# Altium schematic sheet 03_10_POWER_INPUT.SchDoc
size 289 x 400 mm
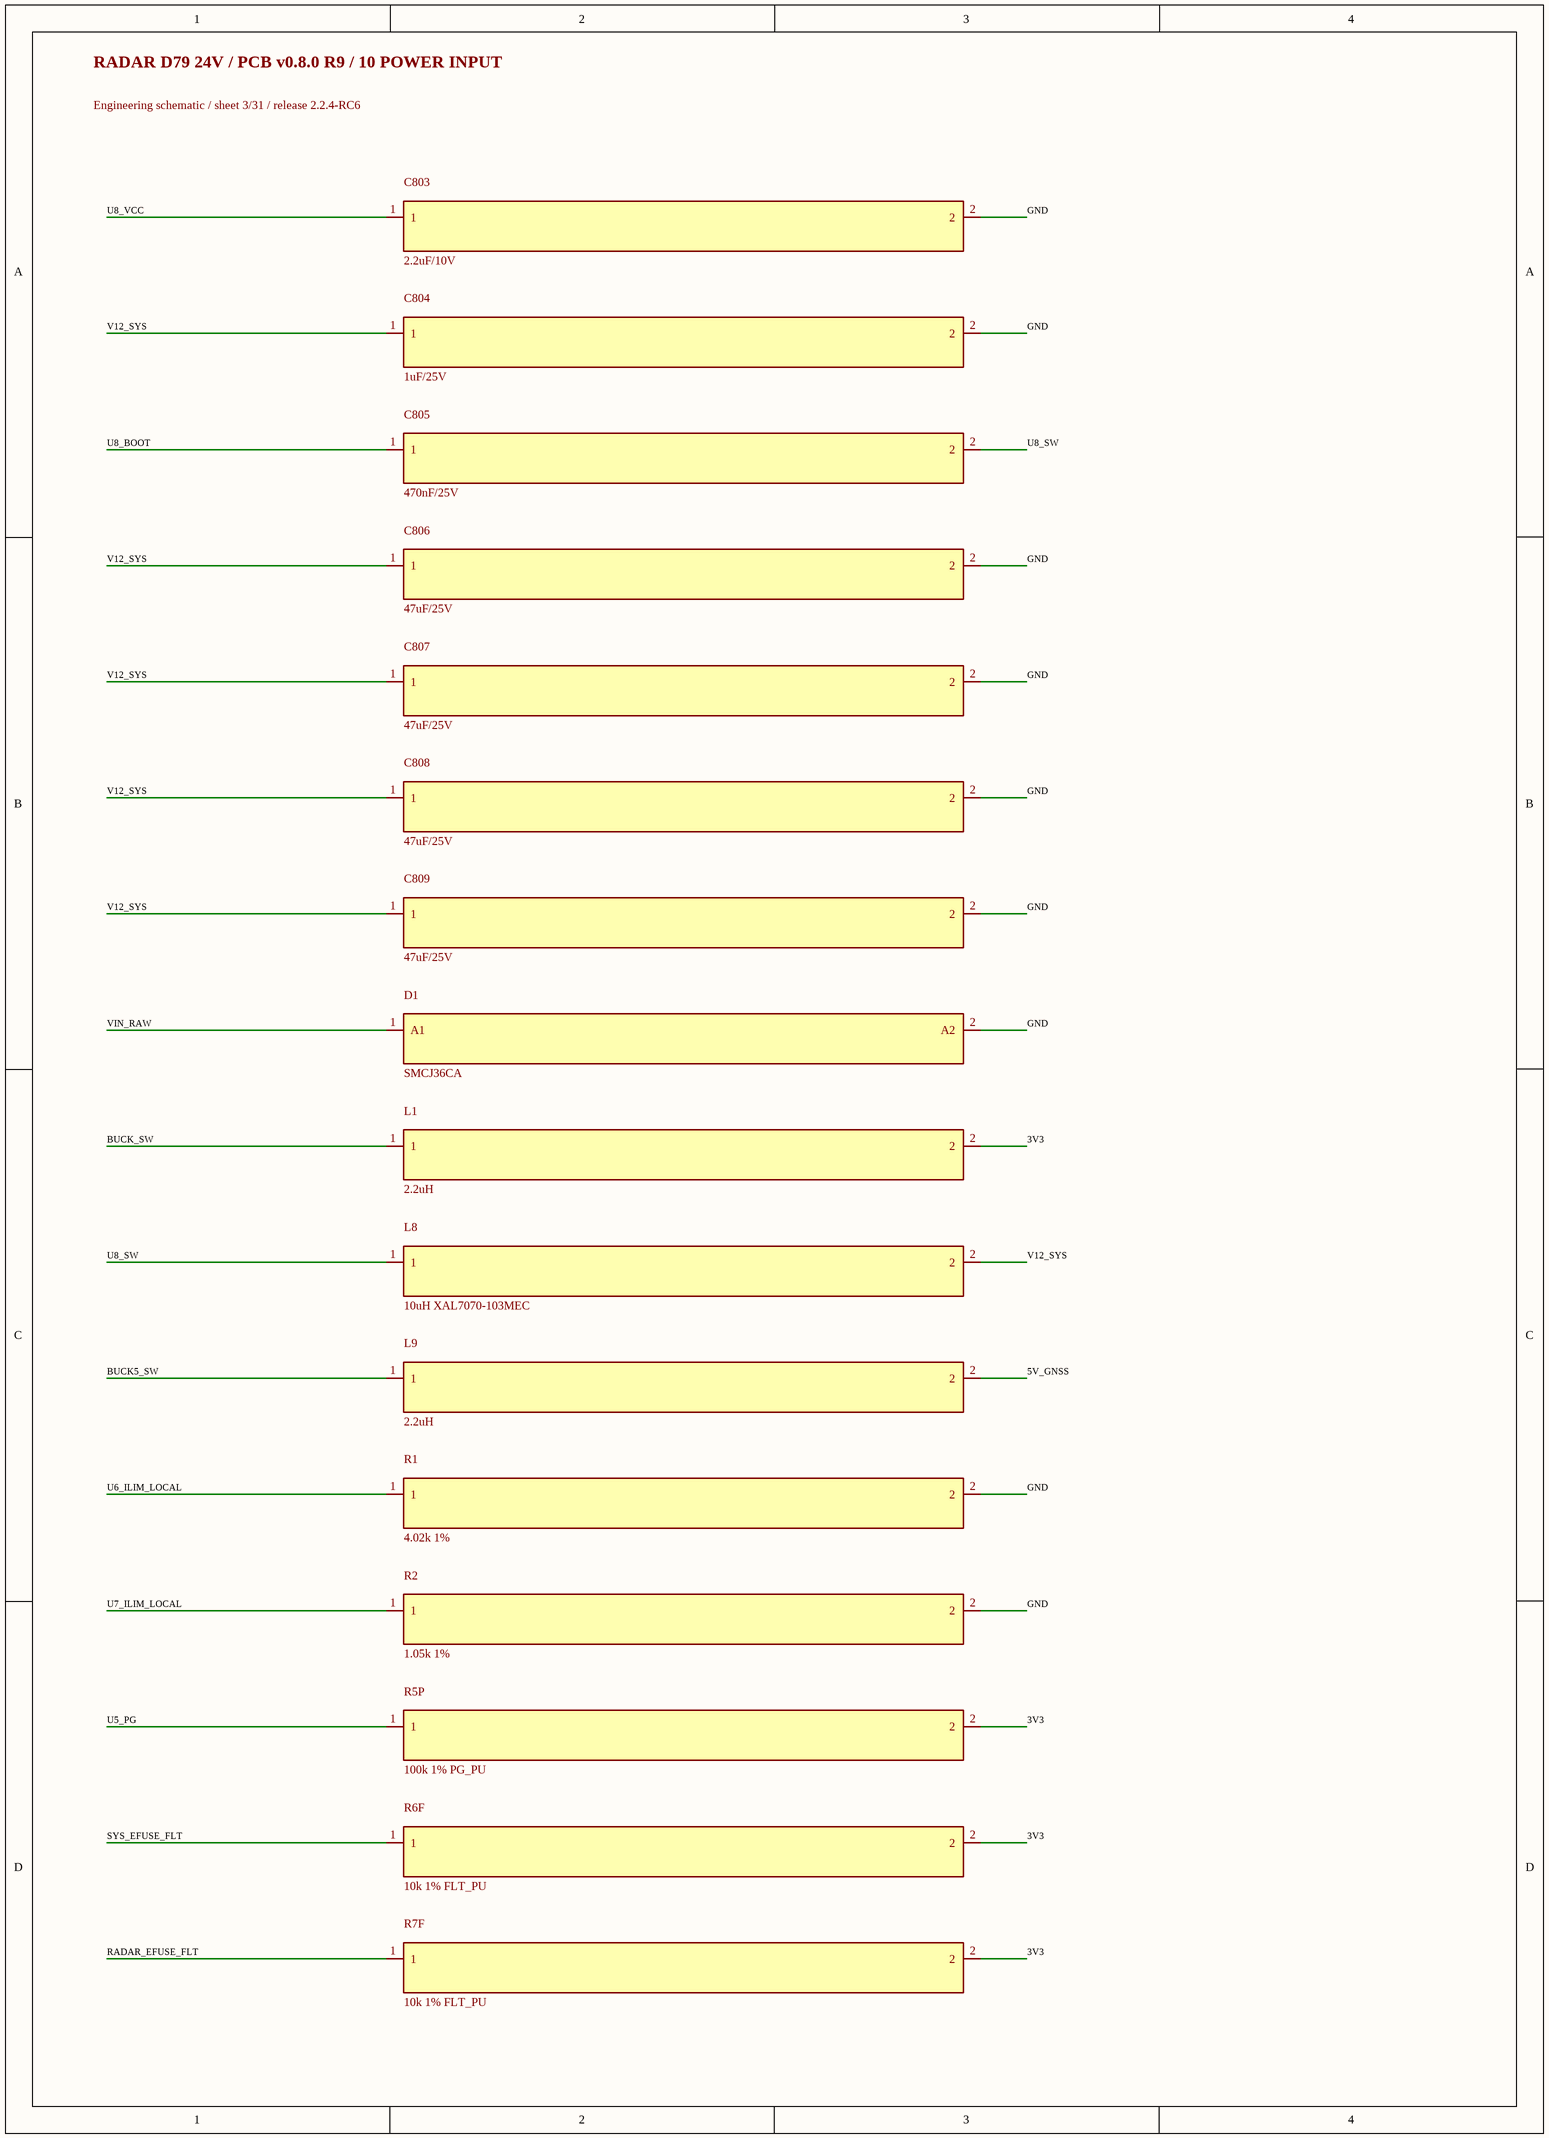
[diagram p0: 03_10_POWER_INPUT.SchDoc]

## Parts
C803  2.2uF/10V  [C_0603_1608Metric]
C804  1uF/25V  [C_0603_1608Metric]
C805  470nF/25V  [C_0603_1608Metric]
C806  47uF/25V  [C_1210_3225Metric]
C807  47uF/25V  [C_1210_3225Metric]
C808  47uF/25V  [C_1210_3225Metric]
C809  47uF/25V  [C_1210_3225Metric]
D1  SMCJ36CA  [D_SMC]
L1  2.2uH  [Coilcraft_XFL4020_4x4]
L8  10uH XAL7070-103MEC  [L_Coilcraft_XAL7070-XXX]
L9  2.2uH  [Coilcraft_XFL4020_4x4]
R1  4.02k 1%  [R_0603_1608Metric]
R2  1.05k 1%  [R_0603_1608Metric]
R5P  100k 1% PG_PU  [R_0603_1608Metric]
R6F  10k 1% FLT_PU  [R_0603_1608Metric]
R7F  10k 1% FLT_PU  [R_0603_1608Metric]

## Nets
3V3: L1.2 R5P.2 R6F.2 R7F.2
5V_GNSS: L9.2
BUCK5_SW: L9.1
BUCK_SW: L1.1
GND: C803.2 C804.2 C806.2 C807.2 C808.2 C809.2 D1.2(A2) R1.2 R2.2
RADAR_EFUSE_FLT: R7F.1
SYS_EFUSE_FLT: R6F.1
U5_PG: R5P.1
U6_ILIM_LOCAL: R1.1
U7_ILIM_LOCAL: R2.1
U8_BOOT: C805.1
U8_SW: C805.2 L8.1
U8_VCC: C803.1
V12_SYS: C804.1 C806.1 C807.1 C808.1 C809.1 L8.2
VIN_RAW: D1.1(A1)

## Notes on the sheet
- RADAR D79 24V / PCB v0.8.0 R9 / 10 POWER INPUT
- Engineering schematic / sheet 3/31 / release 2.2.4-RC6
